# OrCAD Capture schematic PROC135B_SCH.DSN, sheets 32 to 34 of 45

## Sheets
32 32. SOC WKUP & GPMC: size C; title: SOC WKUP AND SOC GPMC INTERFACE
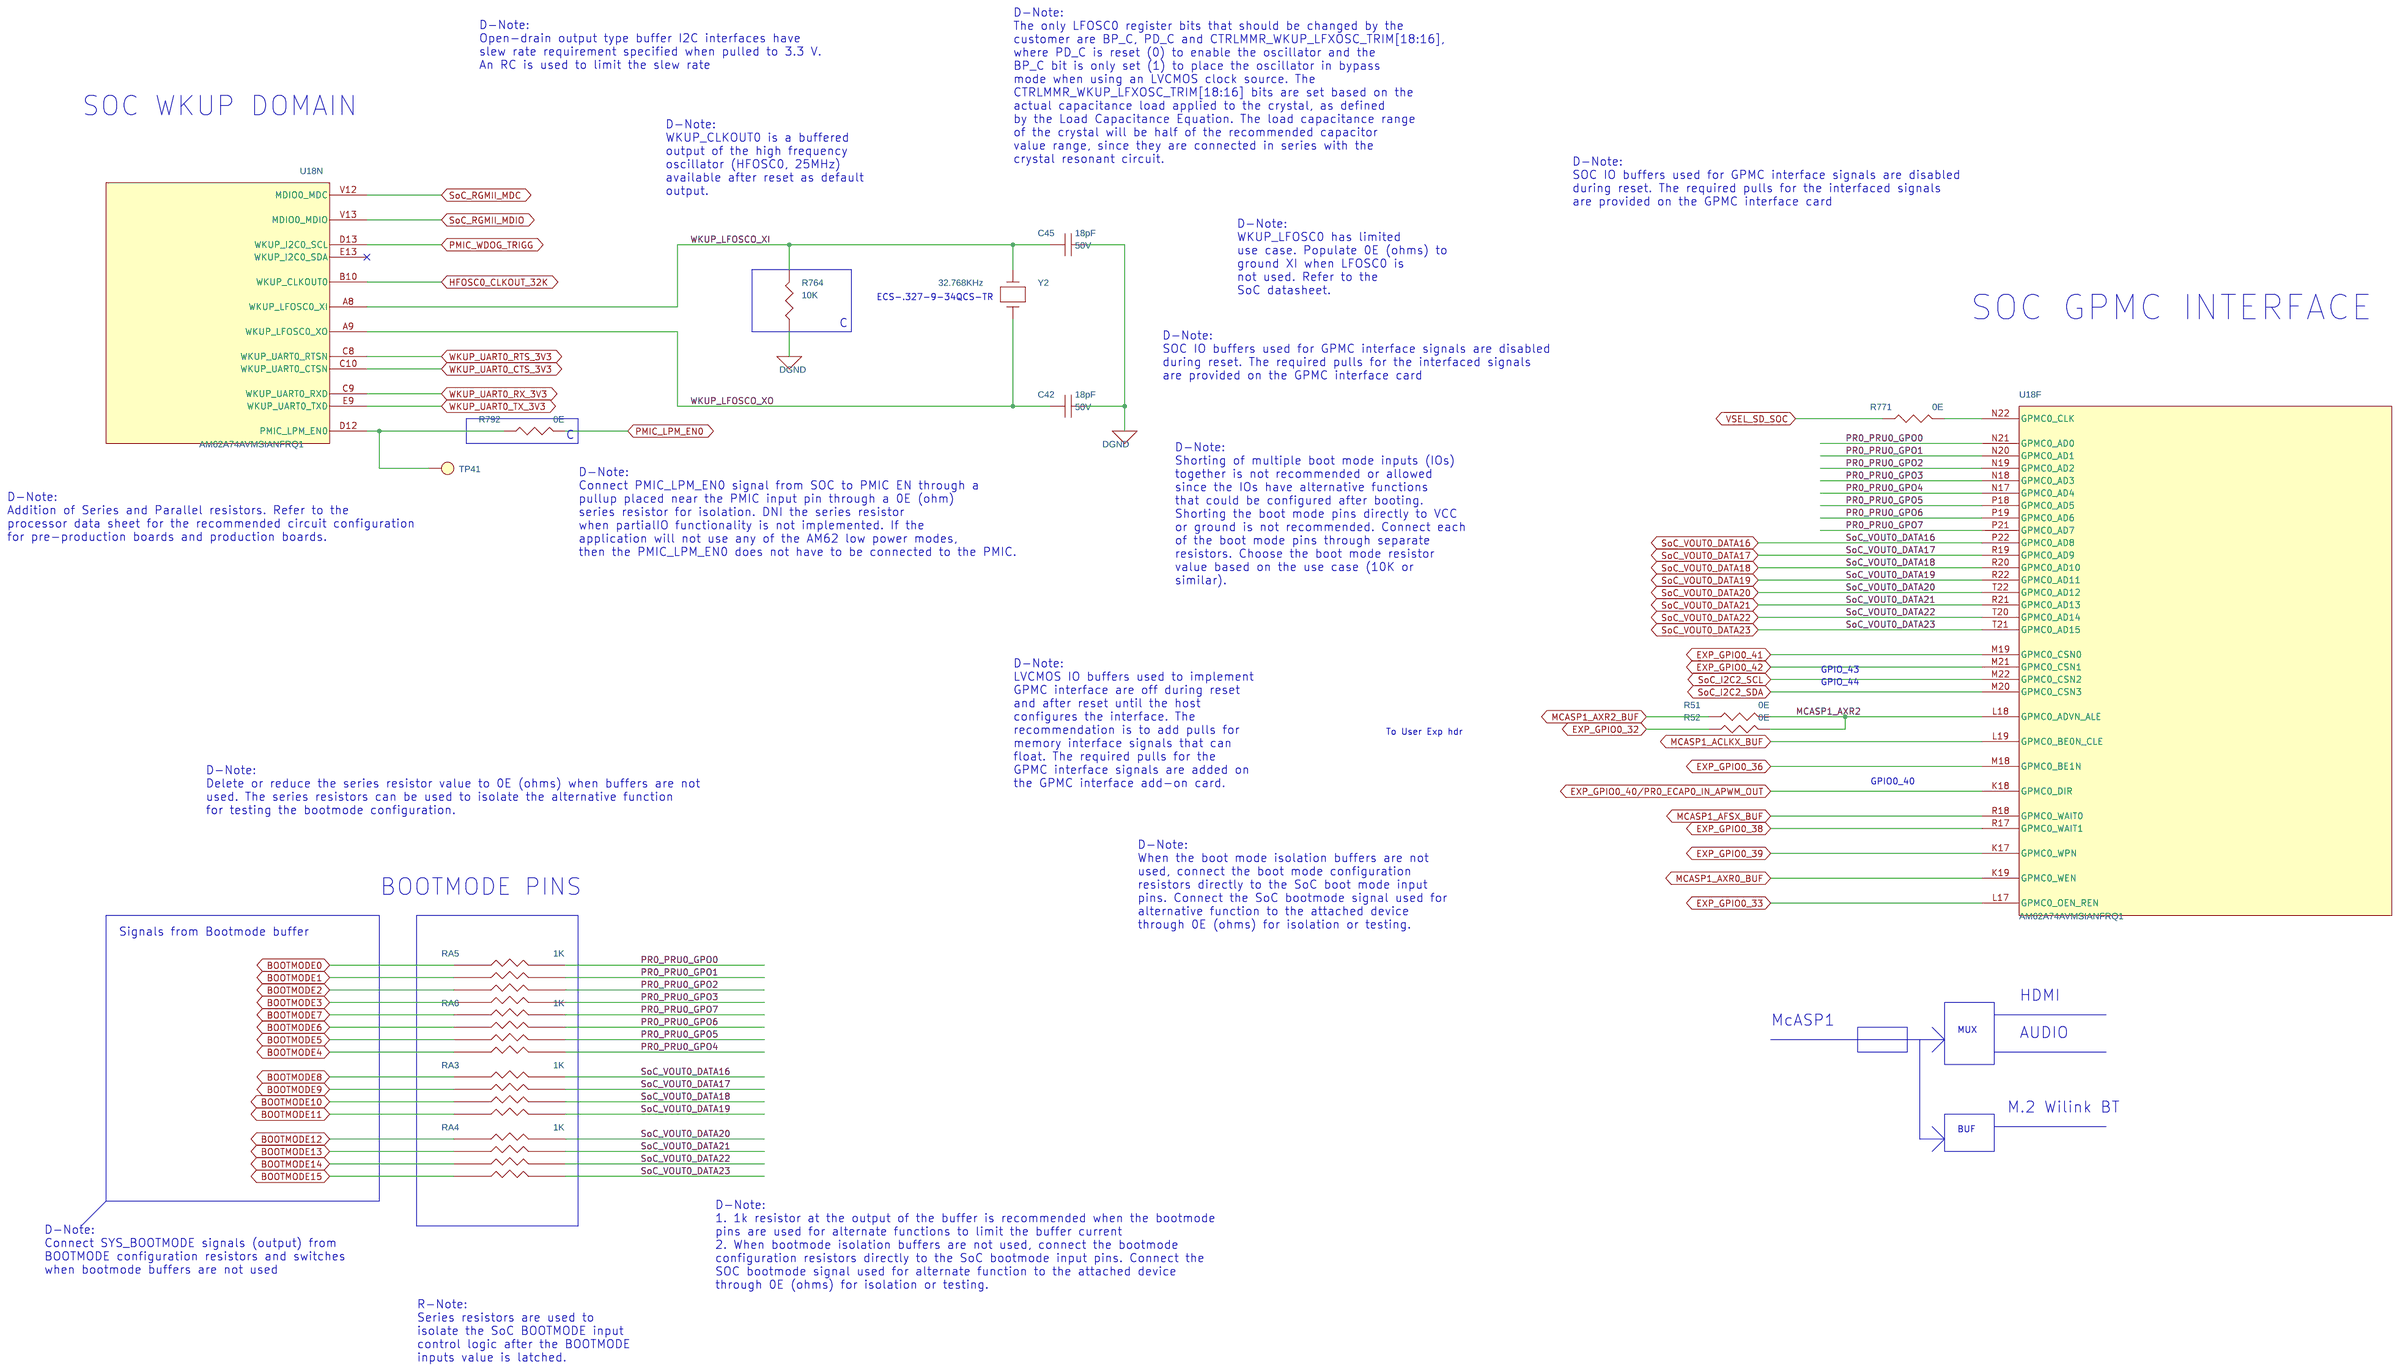
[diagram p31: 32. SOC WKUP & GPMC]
33 33. USER EXPANSION CONNECTOR: size C; title: USER EXPANSION CONNECTOR
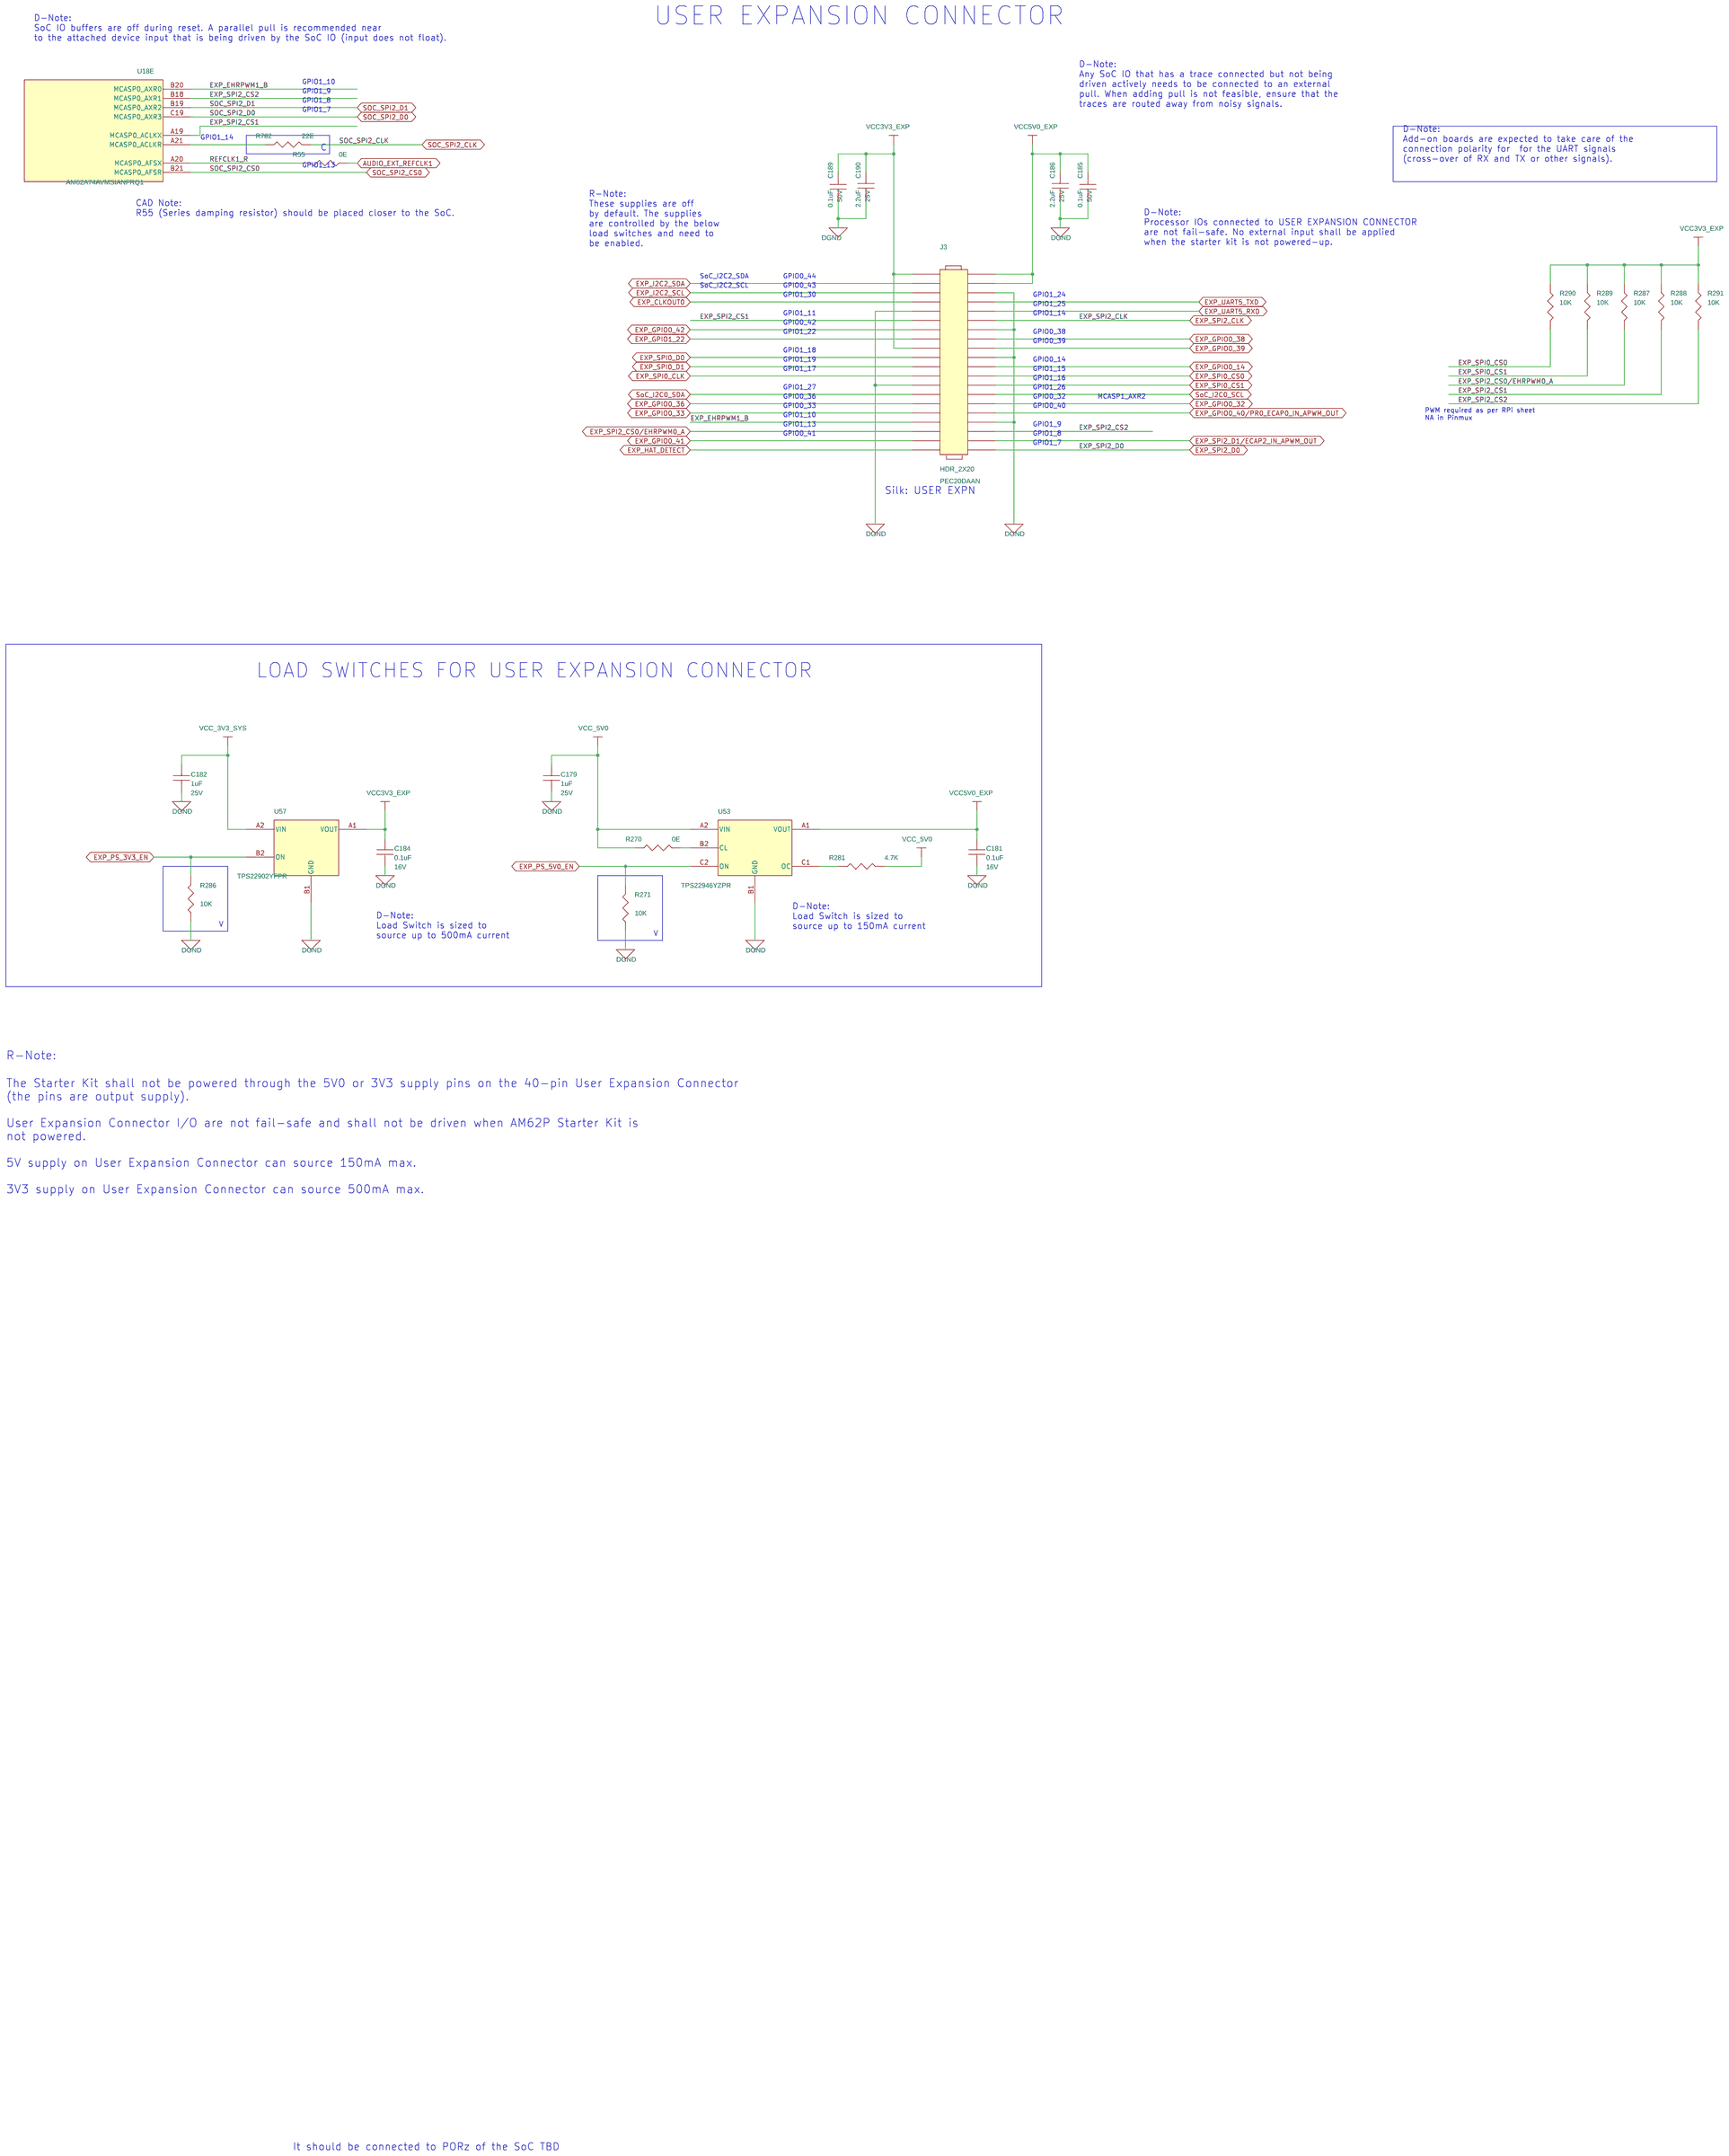
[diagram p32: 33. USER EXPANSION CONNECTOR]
34 34. MCU HEADER: size C; title: SOC-MCU DOMAIN IO and OSC0 AND SOC-MCU IO HEADER
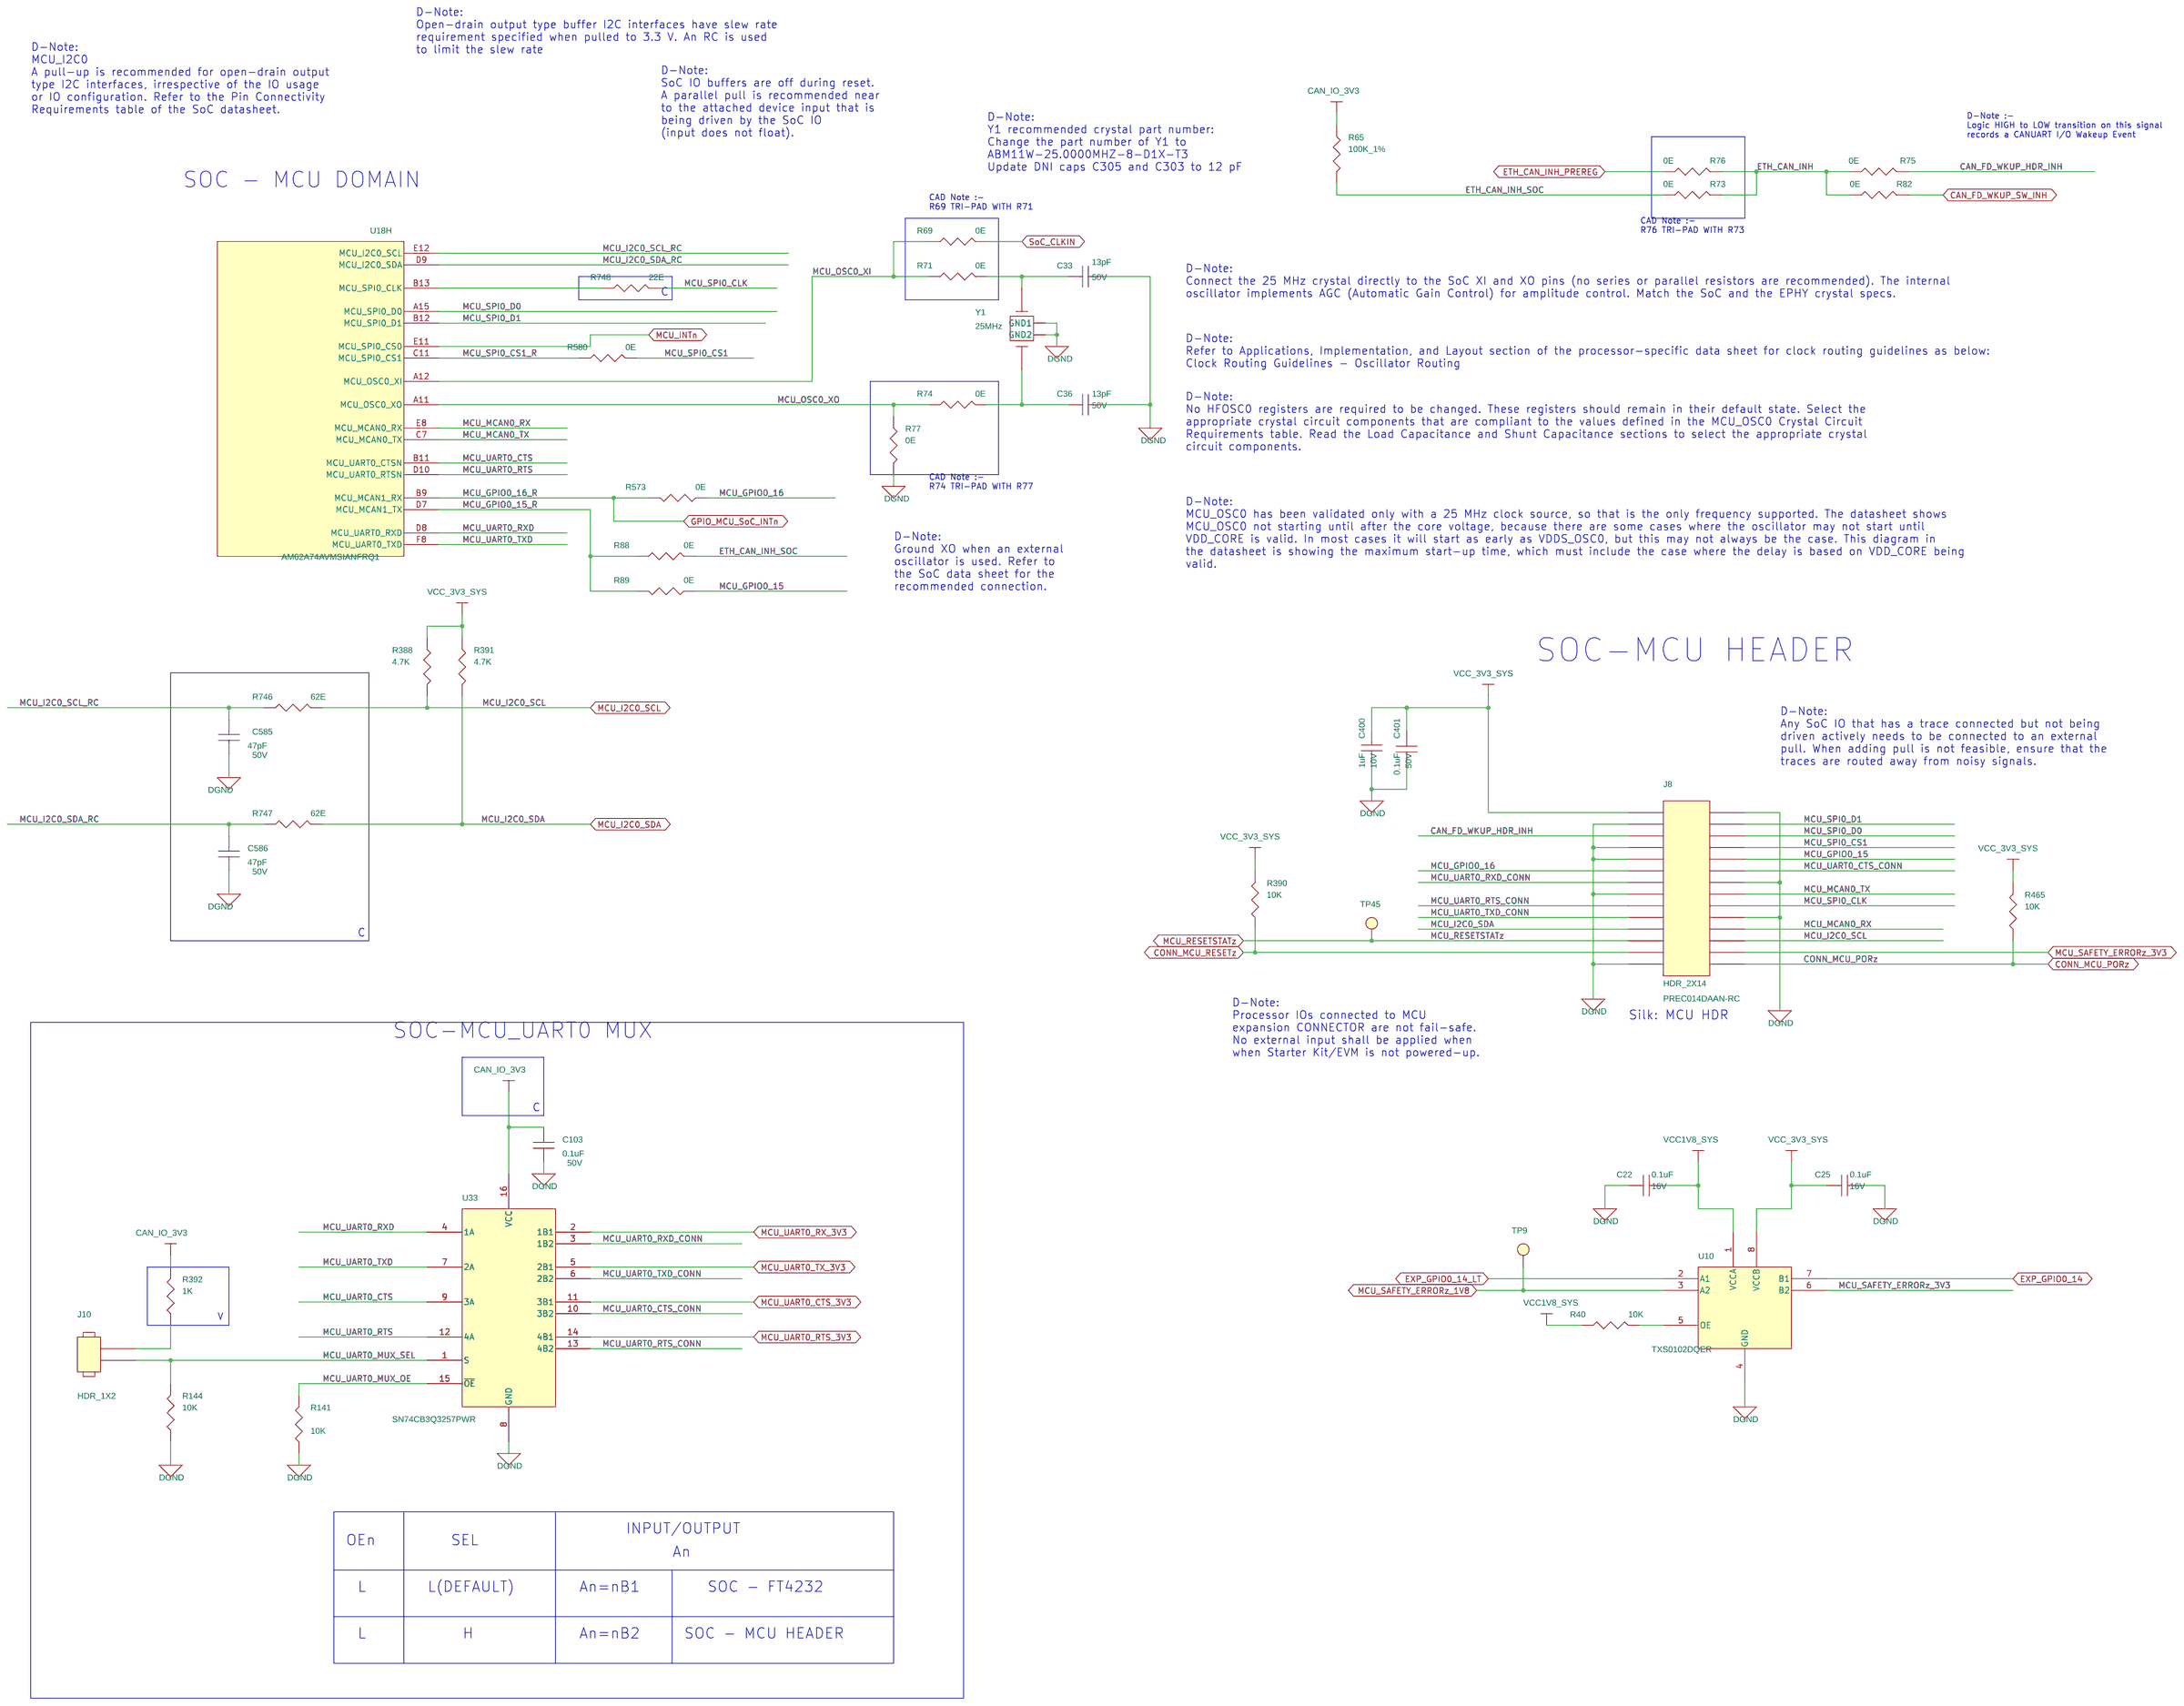
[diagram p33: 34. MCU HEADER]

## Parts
sheet 32. SOC WKUP & GPMC
C42  18pF  [CAP0402_0-75]
C45  18pF  [CAP0402_0-75]
R51  0E  [RES0201_0-5]
R52  0E  [RES0201_0-5]
R764  10K  [RES0201_0-5]
R771  0E  [RES0201_0-5]
R792  0E  [RES0201_0-5]
RA3  1K  [RESA_EXB_0201-4_0-5]
RA4  1K  [RESA_EXB_0201-4_0-5]
RA5  1K  [RESA_EXB_0201-4_0-5]
RA6  1K  [RESA_EXB_0201-4_0-5]
TP41  TP20_SMD  [TP20_SMD]
Y2  32.768KHz  [XTAL_ECS-32_130X60_SMD_0-9]
sheet 33. USER EXPANSION CONNECTOR
C179  1uF  [CAP0402_0-75]
C181  0.1uF  [CAP0201_0-5]
C182  1uF  [CAP0402_0-75]
C184  0.1uF  [CAP0201_0-5]
C185  0.1uF  [CAP0402_0-75]
C186  2.2uF  [CAP0402_0-75]
C189  0.1uF  [CAP0402_0-75]
C190  2.2uF  [CAP0402_0-75]
J3  HDR_2X20  [HDR_2X20_PEC20DAAN_S_T_8-6]
R55  0E  [RES0201_0-5]
R270  0E  [RES0201_0-5]
R271  10K  [RES0201_0-5]
R281  4.7K  [RES0201_0-5]
R286  10K  [RES0201_0-5]
R287  10K  [RES0201_0-5]
R288  10K  [RES0201_0-5]
R289  10K  [RES0201_0-5]
R290  10K  [RES0201_0-5]
R291  10K  [RES0201_0-5]
R782  22E  [RES0201_0-5]
U53  TPS22946YZPR  [DSBGA6_19-68_40X60_0-5]
U57  TPS22902YFPR  [DSBGA4_15-74_30X30_0-5]
sheet 34. MCU HEADER
C22  0.1uF  [CAP0201_0-5]
C25  0.1uF  [CAP0201_0-5]
C33  13pF  [CAP0402_0-75]
C36  13pF  [CAP0402_0-75]
C103  0.1uF  [CAP0402_0-75]
C400  1uF  [CAP0201_0-5]
C401  0.1uF  [CAP0402_0-75]
C585  47pF  [CAP0201_0-5]
C586  47pF  [CAP0201_0-5]
J8  HDR_2X14  [HDR_14X2_100_S_T]
J10  HDR_1X2  [HDR_1X2_90120-0122_S_T_5-6]
R40  10K  [RES0201_0-5]
R65  100K_1%  [RES0402_0-5]
R69  0E  [RES0201_0-5]
R71  0E  [RES0201_0-5]
R73  0E  [RES0201_0-5]
R74  0E  [RES0201_0-5]
R75  0E  [RES0201_0-5]
R76  0E  [RES0201_0-5]
R77  0E  [RES0201_0-5]
R82  0E  [RES0201_0-5]
R88  0E  [RES0201_0-5]
R89  0E  [RES0201_0-5]
R141  10K  [RES0201_0-5]
R144  10K  [RES0201_0-5]
R388  4.7K  [RES0201_0-5]
R390  10K  [RES0201_0-5]
R391  4.7K  [RES0201_0-5]
R392  1K  [RES0402_0-5]
R465  10K  [RES0201_0-5]
R573  0E  [RES0201_0-5]
R580  0E  [RES0201_0-5]
R746  62E  [RES0201_0-5]
R747  62E  [RES0201_0-5]
R748  22E  [RES0201_0-5]
TP9  TP20_SMD  [TP20_SMD]
TP45  TP20_SMD  [TP20_SMD]
U10  TXS0102DQER  [X2SON8_TXS0102_40X60_0-4]
U18  AM62A74AVMSIANFRQ1  [FBGA484_31-49_710X710_2-7]  (sections A,B,C,D,E,F,G,H,I,J,K,L,M,N,O,P,Q)
U33  SN74CB3Q3257PWR  [TSSOP16_25-59_205X180]
Y1  25MHz  [XTAL4_ABM11W_80X70_SMD_0-5]

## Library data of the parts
C42 C45 = CAP: CAP CERAMIC 18pF 50V 5% HI-Q C0G(NP0) AUTO 0402; Chkd/date: PRADEEP/080224; Crtd /date: TAMILARASU/080224; Custom_Duty: 15%; Customs_HS_Code: 85322990; Distributor_name: NA; Distributor_part_number: NA; Footprint Path: Y:\MIS_DATABASE\Library\ALTIUM_TOOL\PCB_FOOTPRINTS\Altium_Footprint_Lib.PcbLib; Height: 0.55MM; Library Path: Y:\MIS_DATABASE\Library\ALTIUM_TOOL\SCHEMATICS_PARTS\MS_DISCRETE_Library.schlib; Mfr_name: MURATA; Mfr_part_number: GCQ1555C1H180JB01; Mistral Part No: 120024020020-R; Package: 0402; Part_type: CAPACITORS\CERAMIC; Project: AM62D_EVM; RoHS: RoHS; Temperature: -55°C+125°C; Tolerance: 5%; Voltage: 50V; Wattage: NA; Weight: NA; Datasheet: Y:\MIS_DATABASE\DATASHEETS\CAPACITORS\GCQ1555C1H180JB01.PDF
R51 R52 R55 R69 R71 R73-R75 R77 R88 R89 R270 R573 R580 R771 R792 = RESISTOR: RES 0E 1/20W 5% 0201; Chkd/date: NAVEED/301214; Crtd /date: MUDDU/120710; Custom_Duty: 15%; Customs_HS_Code: 85332119; Distributor_name: DIGIKEY; Distributor_part_number: 311-0.0NCT-ND; Footprint Path: Y:\MIS_DATABASE\Library\ALTIUM_TOOL\PCB_FOOTPRINTS\Altium_Footprint_Lib.PcbLib; Height: 0.26MM; Library Path: Y:\MIS_DATABASE\Library\ALTIUM_TOOL\SCHEMATICS_PARTS\MS_DISCRETE_Library.schlib; Mfr_name: YAGEO AMERICA; Mfr_part_number: RC0201JR-070RL; Mistral Part No: 110010070067-R; Package: 0201; Part_type: RESISTORS\FIXED; Project: PB_BUGBASE; RoHS: RoHS; Temperature: -55°C+125°C; Tolerance: 5%; Voltage: NA; Wattage: 1/20W; Weight: 0.17mg; Datasheet: Y:\MIS_DATABASE\DATASHEETS\RESISTORS\RCXXXXL-SER_MAR18.PDF
R40 R141 R144 R271 R286-R291 R390 R465 R764 = RESISTOR: RES 10K 1/20W 5% 0201; Chkd/date: MANIRAJA/050517; Crtd /date: MANIRAJA/050517; Custom_Duty: 15%; Customs_HS_Code: 85332119; Distributor_name: DIGIKEY; Distributor_part_number: 311-10KNCT-ND; Footprint Path: Y:\MIS_DATABASE\Library\ALTIUM_TOOL\PCB_FOOTPRINTS\Altium_Footprint_Lib.PcbLib; Height: 0.26MM; Library Path: Y:\MIS_DATABASE\Library\ALTIUM_TOOL\SCHEMATICS_PARTS\MS_DISCRETE_Library.schlib; Mfr_name: YAGEO AMERICA; Mfr_part_number: RC0201JR-0710KL; Mistral Part No: 110010070051-R; Package: 0201; Part_type: RESISTORS\FIXED; Project: GOLDEN-I LITE; RoHS: RoHS; Temperature: -55°C+125°C; Tolerance: 5%; Voltage: NA; Wattage: 1/20W; Weight: 0.17mg; Datasheet: Y:\MIS_DATABASE\DATASHEETS\RESISTORS\RCXXXXL-SER_MAR18.PDF
RA3-RA6 = RESARR_ISO4: RES ARRAY 1K 31mW 5% 0201-4; Chkd/date: NAVEED/110515; Crtd /date: VASANTHA/080515; Custom_Duty: 15%; Customs_HS_Code: 85332119; Distributor_name: DIGIKEY; Distributor_part_number: Y6102CT-ND; Footprint Path: Y:\MIS_DATABASE\Library\ALTIUM_TOOL\PCB_FOOTPRINTS\Altium_Footprint_Lib.PcbLib; Height: 0.45MM; Library Path: Y:\MIS_DATABASE\Library\ALTIUM_TOOL\SCHEMATICS_PARTS\MS_DISCRETE_Library.schlib; Mfr_name: PANASONIC-ECG; Mfr_part_number: EXB-18V102JX; Mistral Part No: 110015050003-R; Package: 0201-4; Part_type: RESISTORS\ARRAY; Project: FREE SCALE NANO; RoHS: RoHS; Temperature: -55°C+125°C; Tolerance: 5%; Voltage: NA; Wattage: 31mW; Weight: 1mg; Datasheet: Y:\MIS_DATABASE\DATASHEETS\RESISTORS\EXB-18V.PDF
TP9 TP41 TP45 = TESTPOINT: TESTPOINT CIR 20 SMD; Chkd/date: SHREESHAIL/171006; Crtd /date: MAZHAR/171006; Custom_Duty: NA; Customs_HS_Code: NA; Distributor_name: NA; Distributor_part_number: NA; Footprint Path: Y:\MIS_DATABASE\Library\ALTIUM_TOOL\PCB_FOOTPRINTS\Altium_Footprint_Lib.PcbLib; Height: NA; Library Path: Y:\MIS_DATABASE\Library\ALTIUM_TOOL\SCHEMATICS_PARTS\MS_DISCRETE_Library.schlib; MECHANICAL 3D STEP FILE: NA; Mfr_name: LOCAL; Mistral Part No: NA; Package: SMD; Project: BT MODULE_CSRBC04; RoHS: NA; Temperature: NA; Tolerance: NA; Voltage: NA; Wattage: NA; Weight: NA; Datasheet: NA
Y2 = CRY: CRY 32.768KHz 9pF SMD; Chkd/date: VASANTHA/090419; Crtd /date: ALVY/090419; Custom_Duty: 24%; Customs_HS_Code: 85439000; Distributor_name: DIGIKEY; Distributor_part_number: XC2160CT-ND; Footprint Path: Y:\MIS_DATABASE\Library\ALTIUM_TOOL\PCB_FOOTPRINTS\Altium_Footprint_Lib.PcbLib; Height: 0.90MM; Library Path: Y:\MIS_DATABASE\Library\ALTIUM_TOOL\SCHEMATICS_PARTS\MS_DISCRETE_Library.schlib; Mfr_name: ECS INC; Mfr_part_number: ECS-.327-9-34QCS-TR; Mistral Part No: 130019040003-R; Package: SMD; Part_type: CRYSTAL; Project: J7ES_SOM_DUAL-LEO_PMIC; RoHS: RoHS; Temperature: -40°C+125°C; Tolerance: NA; Voltage: NA; Wattage: NA; Weight: 16mg; Datasheet: Y:\MIS_DATABASE\DATASHEETS\MISC\CRY_OSC\ECS-34Q.PDF
C179 C182 = CAP: CAP CERAMIC 1uF 25V 10% X5R AUTO 0402; Chkd/date: MANIRAJA/290318; Crtd /date: ALVY/280318; Custom_Duty: 15%; Customs_HS_Code: 85322990; Distributor_name: DIGIKEY; Distributor_part_number: 490-12263-1-ND; Footprint Path: Y:\MIS_DATABASE\Library\ALTIUM_TOOL\PCB_FOOTPRINTS\Altium_Footprint_Lib.PcbLib; Height: 0.55MM; Library Path: Y:\MIS_DATABASE\Library\ALTIUM_TOOL\SCHEMATICS_PARTS\MS_DISCRETE_Library.schlib; Mfr_name: MURATA; Mfr_part_number: GRT155R61E105KE01D; Mistral Part No: 120019040035-R; Package: 0402; Part_type: CAPACITORS\CERAMIC; Project: NPOL_SAR_ADC; RoHS: RoHS; Temperature: -55°C+85°C; Tolerance: 10%; Voltage: 25V; Wattage: NA; Weight: 0.65mg; Datasheet: Y:\MIS_DATABASE\DATASHEETS\CAPACITORS\GRT155R61E105KE01D.PDF
C181 C184 = CAP: CAP CERAMIC 0.1uF 16V 10% X5R 0201; Chkd/date: PRADEEP/130623; Crtd /date: PRADEEP/130623; Custom_Duty: 15%; Customs_HS_Code: 85322990; Distributor_name: NA; Distributor_part_number: NA; Footprint Path: Y:\MIS_DATABASE\Library\ALTIUM_TOOL\PCB_FOOTPRINTS\Altium_Footprint_Lib.PcbLib; Height: 0.33MM; Library Path: Y:\MIS_DATABASE\Library\ALTIUM_TOOL\SCHEMATICS_PARTS\MS_DISCRETE_Library.schlib; Mfr_name: MURATA; Mfr_part_number: GRT033R61C104KE01; Mistral Part No: 120022060019-R; Package: 0201; Part_type: CAPACITORS\CERAMIC; Project: AM62P_SK; RoHS: RoHS; Temperature: -55°C+85°C; Tolerance: 10%; Voltage: 16V; Wattage: NA; Weight: 0.33mg; Datasheet: Y:\MIS_DATABASE\DATASHEETS\CAPACITORS\GRT033R61C104KE01XX.PDF
C103 C185 C189 C401 = CAP: CAP CERAMIC 0.1uF 50V 10% X7R AUTO 0402; Alt_Mfr_name: YAGEO AMERICA; Alt_Mfr_part_number: CC0402KRX5R8BB104; Chkd/date: MANIRAJA/250221; Crtd /date: ALVY/240221; Custom_Duty: 15%; Customs_HS_Code: 85322990; Distributor_name: MOUSER; Distributor_part_number: 81-GRT155R71H104KE1D; Footprint Path: Y:\MIS_DATABASE\Library\ALTIUM_TOOL\PCB_FOOTPRINTS\Altium_Footprint_Lib.PcbLib; Height: 0.55MM; Library Path: Y:\MIS_DATABASE\Library\ALTIUM_TOOL\SCHEMATICS_PARTS\MS_DISCRETE_Library.schlib; Mfr_name: MURATA; Mfr_part_number: GRT155R71H104KE01D; Mistral Part No: 120019030005-R; Package: 0402; Part_type: CAPACITORS\CERAMIC; Project: TI_DRA821 SK EVM BRD; RoHS: RoHS; Temperature: -55°C+125°C; Tolerance: 10%; Voltage: 50V; Wattage: NA; Weight: NA; Datasheet: Y:\MIS_DATABASE\DATASHEETS\CAPACITORS\GRT155R71H104KE01.PDF
C186 C190 = CAP: CAP CERAMIC 2.2uF 25V 10% X5R AUTO 0402; Chkd/date: MANIRAJA/240920; Crtd /date: ALVY/240920; Custom_Duty: 15%; Customs_HS_Code: 85322990; Distributor_name: DIGIKEY; Distributor_part_number: 490-12267-1-ND; Footprint Path: Y:\MIS_DATABASE\Library\ALTIUM_TOOL\PCB_FOOTPRINTS\Altium_Footprint_Lib.PcbLib; Height: 0.70MM; Library Path: Y:\MIS_DATABASE\Library\ALTIUM_TOOL\SCHEMATICS_PARTS\MS_DISCRETE_Library.schlib; Mfr_name: MURATA; Mfr_part_number: GRT155R61E225KE13D; Mistral Part No: 120020090019-R; Package: 0402; Part_type: CAPACITORS\CERAMIC; Project: ECU_RO; RoHS: RoHS; Temperature: -55°C+85°C; Tolerance: 10%; Voltage: 25V; Wattage: NA; Weight: 0.65mg; Datasheet: Y:\MIS_DATABASE\DATASHEETS\CAPACITORS\GRT155R61E225KE13.PDF
J3 = HEADER_20X2: CON HDR 2X20 2.54MM PITCH ST TH; Chkd/date: MANIRAJA/261020; Crtd /date: MANIRAJA/261020; Custom_Duty: 24%; Customs_HS_Code: 85369090; Distributor_name: DIGIKEY; Distributor_part_number: S2012E-20-ND; Footprint Path: Y:\MIS_DATABASE\Library\ALTIUM_TOOL\PCB_FOOTPRINTS\Altium_Footprint_Lib.PcbLib; Height: 8.58MM; Library Path: Y:\MIS_DATABASE\Library\ALTIUM_TOOL\SCHEMATICS_PARTS\MS_CONNECTOR_Library.schlib; Mfr_name: SULLINS CONNECTOR; Mfr_part_number: PEC20DAAN; Mistral Part No: 150020100013-R; Package: THRU-HOLE; Part_type: CONNECTOR\HEADERS; Project: AM64X_SKEVM; RoHS: RoHS; Temperature: -65°C+125°C; Tolerance: NA; Voltage: NA; Wattage: NA; Weight: NA; Datasheet: Y:\MIS_DATABASE\DATASHEETS\CONNECTORS\XXCXXDXXN.PDF
R281 R388 R391 = RESISTOR: RES 4.7K 1/20W 5% 0201; Chkd/date: MANIRAJA/200921; Crtd /date: ALVY/200921; Custom_Duty: 15%; Customs_HS_Code: 85332119; Distributor_name: DIGIKEY; Distributor_part_number: 311-4.7KNCT-ND; Footprint Path: Y:\MIS_DATABASE\Library\ALTIUM_TOOL\PCB_FOOTPRINTS\Altium_Footprint_Lib.PcbLib; Height: 0.26MM; Library Path: Y:\MIS_DATABASE\Library\ALTIUM_TOOL\SCHEMATICS_PARTS\MS_DISCRETE_Library.schlib; Mfr_name: YAGEO AMERICA; Mfr_part_number: RC0201JR-074K7L; Mistral Part No: 110021090007-R; Package: 0201; Part_type: RESISTORS\FIXED; Project: TI_AM62x SKEVM_BRD; RoHS: RoHS; Temperature: -55°C+125°C; Tolerance: 5%; Voltage: NA; Wattage: 1/20W; Weight: 0.17mg; Datasheet: Y:\MIS_DATABASE\DATASHEETS\RESISTORS\RCXXXXL-SER_MAR18.PDF
R748 R782 = RESISTOR: RES 22E 1/20W 5% 0201; Chkd/date: PRADEEP/220424; Crtd /date: SHANKARI/220424; Custom_Duty: 15%; Customs_HS_Code: 85332119; Distributor_name: DIGIKEY; Distributor_part_number: 311-22NCT-ND; Footprint Path: Y:\MIS_DATABASE\Library\ALTIUM_TOOL\PCB_FOOTPRINTS\Altium_Footprint_Lib.PcbLib; Height: 0.26MM; Library Path: Y:\MIS_DATABASE\Library\ALTIUM_TOOL\SCHEMATICS_PARTS\MS_DISCRETE_Library.schlib; Manufacturer: YAGEO; Mfr_name: YAGEO; Mfr_part_number: RC0201JR-0722RL; Mistral Part No: 110024040012-R; Package: 0201; Part_type: RESISTORS\FIXED; Project: J7AEN_SKEVM; RoHS: RoHS; Temperature: -55°C+125°C; Tolerance: 5%; Voltage: NA; Wattage: 1/20W; Weight: NA; Datasheet: Y:\MIS_DATABASE\DATASHEETS\RESISTORS\RC0201JR-0722RL.PDF
U53 = TPS22946_DSBGA6: IC CURRENT-LIMITED LOAD SWITCH WITH SHUTOFF AUTO-RESTART AND OVERCURRENT CONDITION TIME-OUT DSBGA6; Chkd/date: MANIRAJA/220121; Crtd /date: ALVY/220121; Custom_Duty: 15%; Customs_HS_Code: 85423100; Distributor_name: DIGIKEY; Distributor_part_number: 296-25219-1-ND; Footprint Path: Y:\MIS_DATABASE\Library\ALTIUM_TOOL\PCB_FOOTPRINTS\Altium_Footprint_Lib.PcbLib; Height: 0.50MM; Library Path: Y:\MIS_DATABASE\Library\ALTIUM_TOOL\SCHEMATICS_PARTS\MS_MISCPOWER_Library.schlib; Mfr_name: TEXAS INSTRUMENTS; Mistral Part No: 142021010016-R; Package: DSBGA6; Part_type: ICS\POWER\MANAGEMENT; Project: AM64X_SKEVM; RoHS: RoHS; Temperature: -40°C+85°C; Tolerance: NA; Voltage: NA; Wattage: NA; Weight: 1.7mg; Datasheet: Y:\MIS_DATABASE\DATASHEETS\ICS\POWER\TPS22946.PDF
U57 = TPS22912CYZVR_DSBGA4: IC 3.6V 500mA 78mE ON-RESISTANCE LOAD SWITCH WITH CONTROLLED TURNON DSBGA4; Chkd/date: MANIRAJA/170920; Crtd /date: ALVY/160920; Custom_Duty: 15%; Customs_HS_Code: 85423100; Distributor_name: DIGIKEY; Distributor_part_number: 296-24472-1-ND; Footprint Path: Y:\MIS_DATABASE\Library\ALTIUM_TOOL\PCB_FOOTPRINTS\Altium_Footprint_Lib.PcbLib; Height: 0.50MM; Library Path: Y:\MIS_DATABASE\Library\ALTIUM_TOOL\SCHEMATICS_PARTS\MS_MISCPOWER_Library.schlib; Mfr_name: TEXAS INSTRUMENTS; Mistral Part No: 142020090007-R; Package: DSBGA4; Part_type: ICS\POWER; Project: AM64X_SKEVM; RoHS: RoHS; Temperature: -40°C+85°C; Tolerance: NA; Voltage: NA; Wattage: NA; Weight: 0.7mg; Datasheet: Y:\MIS_DATABASE\DATASHEETS\ICS\POWER\TPS22901-2-3.PDF
C22 C25 = CAP: CAP CERAMIC 0.1uF 16V 10% X5R 0201; Alt_Mfr_name: YAGEO AMERICA; Alt_Mfr_part_number: CC0402KRX5R8BB104; Chkd/date: PRADEEP/130623; Crtd /date: PRADEEP/130623; Custom_Duty: 15%; Customs_HS_Code: 85322990; Distributor_name: NA; Distributor_part_number: NA; Footprint Path: Y:\MIS_DATABASE\Library\ALTIUM_TOOL\PCB_FOOTPRINTS\Altium_Footprint_Lib.PcbLib; Height: 0.33MM; Library Path: Y:\MIS_DATABASE\Library\ALTIUM_TOOL\SCHEMATICS_PARTS\MS_DISCRETE_Library.schlib; Mfr_name: MURATA; Mfr_part_number: GRT033R61C104KE01; Mistral Part No: 120022060019-R; Package: 0201; Part_type: CAPACITORS\CERAMIC; Project: AM62P_SK; RoHS: RoHS; Temperature: -55°C+85°C; Tolerance: 10%; Voltage: 16V; Wattage: NA; Weight: 0.33mg; Datasheet: Y:\MIS_DATABASE\DATASHEETS\CAPACITORS\GRT033R61C104KE01XX.PDF
C33 C36 = CAP: CAP CERAMIC 13pF 50V 5% C0G(NP0) 0402; Chkd/date: VASANTHA/090317; Crtd /date: MANIRAJA/090317; Custom_Duty: 15%; Customs_HS_Code: 85322990; Distributor_name: DIGIKEY; Distributor_part_number: 490-5925-1-ND; Footprint Path: Y:\MIS_DATABASE\Library\ALTIUM_TOOL\PCB_FOOTPRINTS\Altium_Footprint_Lib.PcbLib; Height: 0.55MM; Library Path: Y:\MIS_DATABASE\Library\ALTIUM_TOOL\SCHEMATICS_PARTS\MS_DISCRETE_Library.schlib; Mfr_name: MURATA; Mfr_part_number: GRM1555C1H130JA01D; Mistral Part No: 120017030004-R; Package: 0402; Part_type: CAPACITORS\CERAMIC; Project: SD820_NANO_SOM; RoHS: RoHS; Temperature: -55°C+125°C; Tolerance: 5%; Voltage: 50V; Wattage: NA; Weight: 6mg; Datasheet: Y:\MIS_DATABASE\DATASHEETS\CAPACITORS\MURATA-GXX-SER_NOV17.PDF
C400 = CAP: CAP CERAMIC 1uF 10V 20% X6S 0201; Chkd/date: PRADEEP/130623; Crtd /date: PRADEEP/130623; Custom_Duty: 15%; Customs_HS_Code: 85322990; Distributor_name: DIGIKEY; Distributor_part_number: 490-GRT033C81A105ME13DTR-ND; Footprint Path: Y:\MIS_DATABASE\Library\ALTIUM_TOOL\PCB_FOOTPRINTS\Altium_Footprint_Lib.PcbLib; Height: 0.39MM; Library Path: Y:\MIS_DATABASE\Library\ALTIUM_TOOL\SCHEMATICS_PARTS\MS_DISCRETE_Library.schlib; Mfr_name: MURATA; Mfr_part_number: GRT033C81A105ME13D; Mistral Part No: 120022060020-R; Package: 0201; Part_type: CAPACITORS\CERAMIC; Project: AM62P_SK; RoHS: RoHS; Temperature: -55°C+105°C; Tolerance: 20%; Voltage: 10V; Wattage: NA; Weight: NA; Datasheet: Y:\MIS_DATABASE\DATASHEETS\CAPACITORS\GRT033C81A105ME13D.PDF
C585 C586 = CAP: CAP CERAMIC 47pF 50V 5% C0G(NP0) AUTO 0201; Chkd/date: MANIRAJA/311221; Crtd /date: ALVY/301221; Custom_Duty: 15%; Customs_HS_Code: 85322990; Distributor_name: MOUSER; Distributor_part_number: 81-GRT0335C1H470JA2D; Footprint Path: Y:\MIS_DATABASE\Library\ALTIUM_TOOL\PCB_FOOTPRINTS\Altium_Footprint_Lib.PcbLib; Height: 0.33MM; Library Path: Y:\MIS_DATABASE\Library\ALTIUM_TOOL\SCHEMATICS_PARTS\MS_DISCRETE_Library.schlib; Mfr_name: MURATA; Mfr_part_number: GRT0335C1H470JA02D; Mistral Part No: 120021120018-R; Package: 0201; Part_type: CAPACITORS\CERAMIC; Project: AM62Q_SKEVM_BRD; RoHS: RoHS; Temperature: -55°C+125°C; Tolerance: 5%; Voltage: 50V; Wattage: NA; Weight: 0.33mg; Datasheet: Y:\MIS_DATABASE\DATASHEETS\CAPACITORS\GRT0335C1H470JA02.PDF
J8 = HEADER_14x2: CON HDR 2X14 2.54MM PITCH ST TH; Chkd/date: NAVEED/280515; Crtd /date: VASANTHA/111114; Custom_Duty: 0.24; Customs_HS_Code: 85369090; Distributor_name: DIGIKEY; Distributor_part_number: S2012EC-14-ND; Height: 8.34MM; Mfr_name: SULLINS; Mfr_part_number: PREC014DAAN-RC; Mistral Part No: 150014110005-R; Package: THRU-HOLE; Part_type: CONNECTOR\HEADERS; Project: GALILEO_EVM; RoHS: RoHS; Temperature: -40°C+105°C; Tolerance: NA; Voltage: NA; Wattage: NA; Weight: NA; Datasheet: Y:\MIS_DATABASE\DATASHEETS\CONNECTORS\PRXXXN-RC.PDF
J10 = HEADER_2X1: CON HDR 1X2 2.54MM PITCH ST TH; Chkd/date: NAVEED/210714; Crtd /date: USMAN/031012; Custom_Duty: 24%; Customs_HS_Code: 85369090; Distributor_name: DIGIKEY; Distributor_part_number: WM8072-ND; Footprint Path: Y:\MIS_DATABASE\Library\ALTIUM_TOOL\PCB_FOOTPRINTS\Altium_Footprint_Lib.PcbLib; Height: 5.60MM; Library Path: Y:\MIS_DATABASE\Library\ALTIUM_TOOL\SCHEMATICS_PARTS\MS_CONNECTOR_Library.schlib; Mfr_name: MOLEX; Mfr_part_number: 90120-0122; Mistral Part No: 150012100005-R; Package: THRU-HOLE; Part_type: CONNECTOR\HEADERS; Project: NPOL_FEP; RoHS: RoHS; Temperature: -55°C+125°C; Tolerance: NA; Voltage: NA; Wattage: NA; Weight: 122mg; Datasheet: Y:\MIS_DATABASE\DATASHEETS\CONNECTORS\90120-XX.PDF
R65 = RESISTOR: RES 100K 1/10W 1% 0402; Chkd/date: VASANTHA/201216; Crtd /date: MAZHAR/130306; Custom_Duty: 15%; Customs_HS_Code: 85332119; Distributor_name: DIGIKEY; Distributor_part_number: P100KLCT-ND; Footprint Path: Y:\MIS_DATABASE\Library\ALTIUM_TOOL\PCB_FOOTPRINTS\Altium_Footprint_Lib.PcbLib; Height: 0.40MM; Library Path: Y:\MIS_DATABASE\Library\ALTIUM_TOOL\SCHEMATICS_PARTS\MS_DISCRETE_Library.schlib; Mfr_name: PANASONIC-ECG; Mfr_part_number: ERJ-2RKF1003X; Mistral Part No: 110009030187-R; Package: 0402; Part_type: RESISTORS\FIXED; Project: J32; RoHS: RoHS; Temperature: -55°C+155°C; Tolerance: 1%; Voltage: NA; Wattage: 1/10W; Weight: 0.8mg; Datasheet: Y:\MIS_DATABASE\DATASHEETS\RESISTORS\PAN-ERJSER_NOV17.PDF
R76 R82 = RESISTOR: RES 0E 1/20W 5% 0201; Chkd/date: NAVEED/301214; Crtd /date: MUDDU/120710; Custom_Duty: 15%; Customs_HS_Code: 85332119; Distributor_name: DIGIKEY; Distributor_part_number: 311-0.0NCT-ND; Footprint Path: Y:\MIS_DATABASE\Library\ALTIUM_TOOL\PCB_FOOTPRINTS\Altium_Footprint_Lib.PcbLib; Height: 0.26MM; Library Path: Y:\MIS_DATABASE\Library\ALTIUM_TOOL\SCHEMATICS_PARTS\MS_DISCRETE_Library.schlib; Manufacturer: YAGEO AMERICA; Mfr_name: YAGEO AMERICA; Mfr_part_number: RC0201JR-070RL; Mistral Part No: 110010070067-R; Package: 0201; Part_type: RESISTORS\FIXED; Project: PB_BUGBASE; RoHS: RoHS; Temperature: -55°C+125°C; Tolerance: 5%; Voltage: NA; Wattage: 1/20W; Weight: 0.17mg; Datasheet: Y:\MIS_DATABASE\DATASHEETS\RESISTORS\RCXXXXL-SER_MAR18.PDF
R392 = RESISTOR: RES 1K 1/10W 5% 0402; Chkd/date: VASANTHA/201216; Crtd /date: MAZHAR/230805; Custom_Duty: 15%; Customs_HS_Code: 85332119; Distributor_name: DIGIKEY; Distributor_part_number: P1.0KJCT-ND; Footprint Path: Y:\MIS_DATABASE\Library\ALTIUM_TOOL\PCB_FOOTPRINTS\Altium_Footprint_Lib.PcbLib; Height: 0.40MM; Library Path: Y:\MIS_DATABASE\Library\ALTIUM_TOOL\SCHEMATICS_PARTS\MS_DISCRETE_Library.schlib; Mfr_name: PANASONIC-ECG; Mfr_part_number: ERJ-2GEJ102X; Mistral Part No: 110009030400-R; Package: 0402; Part_type: RESISTORS\FIXED; Project: HSE; RoHS: RoHS; Temperature: -55°C+155°C; Tolerance: 5%; Voltage: NA; Wattage: 1/10W; Weight: 0.8mg; Datasheet: Y:\MIS_DATABASE\DATASHEETS\RESISTORS\PAN-ERJSER_NOV17.PDF
R746 R747 = RESISTOR: RES 62E 1/20W 1% 0201; Chkd/date: PRADEEP/230326; Crtd /date: SHANKARI/230326; Custom_Duty: 15%; Customs_HS_Code: 85332119; Distributor_name: DIGIKEY; Distributor_part_number: P123108CT-ND; Footprint Path: Y:\MIS_DATABASE\Library\ALTIUM_TOOL\PCB_FOOTPRINTS\Altium_Footprint_Lib.PcbLib; Height: 0.26MM; Library Path: Y:\MIS_DATABASE\Library\ALTIUM_TOOL\SCHEMATICS_PARTS\MS_DISCRETE_Library.schlib; Mfr_name: PANASONIC; Mfr_part_number: ERJ-1GNF62R0C; Mistral Part No: 110026030006-R; Package: 0201; Part_type: RESISTORS\FIXED; Project: AM62X_FULTON_REV B; RoHS: RoHS; Temperature: -55°C+125°C; Tolerance: 0.01; Voltage: NA; Wattage: 1/20W; Weight: NA; Datasheet: Y:\MIS_DATABASE\DATASHEETS\RESISTORS\ERJ-1GNF62R0C.PDF
U10 = TXS0102DQX_SON8: IC 2-BIT BI-DIR VOLTAGE-LEVEL TRANSLATOR FOR OPEN-DRAIN AND PUSH-PULL X2SON8; Chkd/date: MANIRAJA/010719; Crtd /date: CHAITHANYA230512; Custom_Duty: 15%; Customs_HS_Code: 85423100; Distributor_name: DIGIKEY; Distributor_part_number: 296-28368-1-ND; Footprint Path: Y:\MIS_DATABASE\Library\ALTIUM_TOOL\PCB_FOOTPRINTS\Altium_Footprint_Lib.PcbLib; Height: 0.40MM; Library Path: Y:\MIS_DATABASE\Library\ALTIUM_TOOL\SCHEMATICS_PARTS\MS_MISCINTERFACE_Library.schlib; Mfr_name: TEXAS INSTRUMENTS; Mistral Part No: 141012050010-R; Package: X2SON8; Part_type: ICS\INTERFACE\LEVEL TRANSLATOR; Project: GEN_3-8_DB; RoHS: RoHS; Temperature: -40°C+85°C; Tolerance: NA; Voltage: NA; Wattage: NA; Weight: 1.2mg; Datasheet: Y:\MIS_DATABASE\DATASHEETS\ICS\INTERFACE\TXS0102-SER.PDF
U18 = AM62A-EVM_SOC_FCBGA484: IC AM62A SK EVM SoC MICROPROCESSOR FCBGA484; Chkd/date: PRADEEP/120225; Crtd /date: SHANKARI/120225; Custom_Duty: 15%; Customs_HS_Code: 85369090; Distributor_name: NA; Distributor_part_number: NA; Footprint Path: Y:\MIS_DATABASE\Library\ALTIUM_TOOL\PCB_FOOTPRINTS\Altium_Footprint_Lib.PcbLib; Height: 2.65MM; Library Path: Y:\MIS_DATABASE\Library\ALTIUM_TOOL\SCHEMATICS_PARTS\MS_MICROPROCESSOR_Library.schlib; Library Ref: AM62A-EVM_SoC_FCBGA484; Mfr_name: TEXAS INSTRUMENTS; Mistral Part No: 141225020003-R; Package: FCBGA484; Part_type: ICS\DIGITAL\MICROPROCESSOR; Project: AM62A_SK_EVM; RoHS: NA; Temperature: NA; Tolerance: NA; Voltage: NA; Wattage: NA; Weight: NA; Datasheet: Y:\MIS_DATABASE\DATASHEETS\ICS\DIGITAL\MICROCONTROLLER\AM62A_SK_EVM.PDF
U33 = SN74CB3Q3257PWR_TSSOP16: IC 4BIT 1-OF-2 FET MULTIPLEXER/DEMULTIPLEXER TSSOP16; Chkd/date: SUHAS/251010; Crtd /date: USMAN/060109; Custom_Duty: 15%; Customs_HS_Code: 85423100; Distributor_name: DIGIKEY; Distributor_part_number: 296-19138-1-ND; Height: 1.20MM; Mfr_name: TEXAS INSTRUMENTS; Mistral Part No: 141009030117-R; Package: TSSOP16; Part_type: ICS\DIGITAL\COMBINATIONAL; Project: OMAP_EVM; RoHS: Sb/ Br FREE; Temperature: -40°C+85°C; Datasheet: Y:\MIS_DATABASE\DATASHEETS\ICS\DIGITAL\COMBINATIONAL\SN74CB3Q3257.PDF
Y1 = CRY4_ABM8G: CRY 25MHz 8pF SMD; Crtd /date: SHANKARI/041125; Custom_Duty: 24%; Customs_HS_Code: 85439000; Distributor_name: DIGIKEY; Distributor_part_number: 535-13853-1-ND; Footprint Path: Y:\MIS_DATABASE\Library\ALTIUM_TOOL\PCB_FOOTPRINTS\Altium_Footprint_Lib.PcbLib; Height: 0.50MM; Library Path: Y:\MIS_DATABASE\Library\ALTIUM_TOOL\SCHEMATICS_PARTS\MS_DISCRETE_Library.schlib; Mfr_name: ABRACON CORPORATION; Mfr_part_number: ABM11W-25.0000MHZ-8-D1X-T3; Mistral Part No: 130025110002-R; Package: SMD; Part_type: CRYSTAL; Project: AM62X_SK_FULTON; RoHS: RoHS; Temperature: -40°C+85°C; Tolerance: NA; Voltage: NA; Wattage: NA; Weight: NA; Datasheet: Y:\MIS_DATABASE\DATASHEETS\MISC\CRY_OSC\ABM11W.PDF

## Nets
DGND: C22.2 C25.1 C33.2 C36.2 C42.2 C45.2 C103.1 C179.2 C181.2 C182.2 C184.2 C185.1 C186.2 C189.1 C190.2 C400.2 C401.1 C585.1 C586.1 J3.6 J3.9 J3.14 J3.20 J3.25 J3.34 J8.2 J8.3 J8.7 J8.9 J8.14 J8.15 J8.20 J8.27 R77.1 R141.2 R144.1 R271.1 R286.1 R764.1 U10.4(GND) U33.8(GND) U53.B1(GND) U57.B1(GND) Y1.2(GND1) Y1.4(GND2) ; also on sheet 10 11 12 13 14 15 16 17 18 19 20 21 22 23 24 25 26 27 28 29 30 31 35 36 37 38 39 40 41 42 43 44
VCC1V8_SYS: C22.1 R40.1 U10.1(VCCA) ; also on sheet 13 18 19 21 37 39 40 42
VCC3V3_EXP: C184.1 C189.2 C190.1 J3.1 J3.17 R287.1 R288.1 R289.1 R290.1 R291.1 U57.A1(VOUT) ; also on sheet 38
VCC5V0_EXP: C181.1 C185.2 C186.1 J3.2 J3.4 U53.A1(VOUT)
VCC_3V3_SYS: C25.2 C182.1 C400.1 C401.2 J8.1 R388.1 R390.2 R391.1 R465.2 U10.8(VCCB) U57.A2(VIN) ; also on sheet 10 11 13 14 18 19 20 22 23 24 26 27 29 30 31 35 36 37 38 39 40 41 42 43
VCC_5V0: C179.1 R270.1 R281.2 U53.A2(VIN) ; also on sheet 10 11 15 35 38 41
AUDIO_EXT_REFCLK1: R55.1 ; also on sheet 41
BOOTMODE0: RA5.1 ; also on sheet 27
BOOTMODE1: RA5.2 ; also on sheet 27
BOOTMODE2: RA5.3 ; also on sheet 27
BOOTMODE3: RA5.4 ; also on sheet 27
BOOTMODE4: RA6.4 ; also on sheet 27
BOOTMODE5: RA6.3 ; also on sheet 27
BOOTMODE6: RA6.2 ; also on sheet 27
BOOTMODE7: RA6.1 ; also on sheet 27
BOOTMODE8: RA3.1 ; also on sheet 27
BOOTMODE9: RA3.2 ; also on sheet 27
BOOTMODE10: RA3.3 ; also on sheet 27
BOOTMODE11: RA3.4 ; also on sheet 27
BOOTMODE12: RA4.1 ; also on sheet 27
BOOTMODE13: RA4.2 ; also on sheet 27
BOOTMODE14: RA4.3 ; also on sheet 27
BOOTMODE15: RA4.4 ; also on sheet 27
CAN_FD_WKUP_HDR_INH: J8.5 R75.1
CAN_FD_WKUP_SW_INH: R82.2 ; also on sheet 44
CAN_IO_3V3: C103.2 R65.1 R392.2 U33.16(VCC) ; also on sheet 13 15 31 44
CONN_MCU_PORz: J8.28 R465.1 ; also on sheet 42
CONN_MCU_RESETz: J8.25 R390.1 ; also on sheet 43
ETH_CAN_INH: R73.2 R75.2 R76.2 R82.1
ETH_CAN_INH_PREREG: R76.1 ; also on sheet 12
ETH_CAN_INH_SOC: R65.2 R73.1 R88.1
EXP_CLKOUT0: J3.7 ; also on sheet 42
EXP_EHRPWM1_B: J3.33 U18.B20(MCASP0_AXR0)
EXP_GPIO0_14: J3.22 U10.7(B1)
EXP_GPIO0_14_LT: U10.2(A1) ; also on sheet 21
EXP_GPIO0_32: J3.30 R52.1
EXP_GPIO0_33: J3.31 U18.L17(GPMC0_OEN_REN)
EXP_GPIO0_36: J3.29 U18.M18(GPMC0_BE1N)
EXP_GPIO0_38: J3.16 U18.R17(GPMC0_WAIT1)
EXP_GPIO0_39: J3.18 U18.K17(GPMC0_WPN)
EXP_GPIO0_40/PR0_ECAP0_IN_APWM_OUT: J3.32 U18.K18(GPMC0_DIR)
EXP_GPIO0_41: J3.37 U18.M19(GPMC0_CSN0)
EXP_GPIO0_42: J3.13 U18.M21(GPMC0_CSN1)
EXP_GPIO1_22: J3.15 ; also on sheet 42
EXP_HAT_DETECT: J3.39 ; also on sheet 40
EXP_I2C2_SCL: J3.5 ; also on sheet 38
EXP_I2C2_SDA: J3.3 ; also on sheet 38
EXP_PS_3V3_EN: R286.2 U57.B2(ON) ; also on sheet 40
EXP_PS_5V0_EN: R271.2 U53.C2(ON) ; also on sheet 40
EXP_SPI0_CLK: J3.23 ; also on sheet 42
EXP_SPI0_CS0: J3.24 R290.2 ; also on sheet 42
EXP_SPI0_CS1: J3.26 R289.2 ; also on sheet 42
EXP_SPI0_D0: J3.19 ; also on sheet 42
EXP_SPI0_D1: J3.21 ; also on sheet 42
EXP_SPI2_CLK: J3.12 ; also on sheet 37
EXP_SPI2_CS0/EHRPWM0_A: J3.35 R287.2 ; also on sheet 37
EXP_SPI2_CS1: J3.11 R288.2 U18.A19(MCASP0_ACLKX)
EXP_SPI2_CS2: J3.36 R291.2 U18.B18(MCASP0_AXR1)
EXP_SPI2_D0: J3.40 ; also on sheet 37
EXP_SPI2_D1/ECAP2_IN_APWM_OUT: J3.38 ; also on sheet 37
EXP_UART5_RXD: J3.10 ; also on sheet 42
EXP_UART5_TXD: J3.8 ; also on sheet 42
GPIO_MCU_SoC_INTn: R573.1 U18.B9(MCU_MCAN1_RX) ; also on sheet 43
HFOSC0_CLKOUT_32K: U18.B10(WKUP_CLKOUT0) ; also on sheet 18
MCASP1_ACLKX_BUF: U18.L19(GPMC0_BE0N_CLE) ; also on sheet 40
MCASP1_AFSX_BUF: U18.R18(GPMC0_WAIT0) ; also on sheet 40
MCASP1_AXR0_BUF: U18.K19(GPMC0_WEN) ; also on sheet 40
MCASP1_AXR2: R51.2 R52.2 U18.L18(GPMC0_ADVN_ALE)
MCASP1_AXR2_BUF: R51.1 ; also on sheet 40
MCU_GPIO0_15: J8.10 R89.2
MCU_GPIO0_15_R: R88.2 R89.1 U18.D7(MCU_MCAN1_TX)
MCU_GPIO0_16: J8.11 R573.2
MCU_I2C0_SCL: J8.24 R388.2 R746.2 ; also on sheet 13
MCU_I2C0_SCL_RC: C585.2 R746.1 U18.E12(MCU_I2C0_SCL)
MCU_I2C0_SDA: J8.21 R391.2 R747.2 ; also on sheet 13
MCU_I2C0_SDA_RC: C586.2 R747.1 U18.D9(MCU_I2C0_SDA)
MCU_INTn: U18.E11(MCU_SPI0_CS0) ; also on sheet 13
MCU_MCAN0_RX: J8.22 U18.E8(MCU_MCAN0_RX)
MCU_MCAN0_TX: J8.16 U18.C7(MCU_MCAN0_TX)
MCU_OSC0_XI: R69.2 R71.2 U18.A12(MCU_OSC0_XI)
MCU_OSC0_XO: R74.2 R77.2 U18.A11(MCU_OSC0_XO)
MCU_RESETSTATz: J8.23 TP45.1(TP) ; also on sheet 42
MCU_SAFETY_ERRORz_1V8: TP9.1(TP) U10.3(A2) ; also on sheet 42
MCU_SAFETY_ERRORz_3V3: J8.26 U10.6(B2) ; also on sheet 13
MCU_SPI0_CLK: J8.18 R748.2
MCU_SPI0_CS1: J8.8 R580.1
MCU_SPI0_CS1_R: R580.2 U18.C11(MCU_SPI0_CS1)
MCU_SPI0_D0: J8.6 U18.A15(MCU_SPI0_D0)
MCU_SPI0_D1: J8.4 U18.B12(MCU_SPI0_D1)
MCU_UART0_CTS: U18.B11(MCU_UART0_CTSN) U33.9(3A)
MCU_UART0_CTS_3V3: U33.11(3B1) ; also on sheet 31
MCU_UART0_CTS_CONN: J8.12 U33.10(3B2)
MCU_UART0_MUX_OE: R141.1 U33.15(~{OE})
MCU_UART0_MUX_SEL: J10.2 R144.2 U33.1(S)
MCU_UART0_RTS: U18.D10(MCU_UART0_RTSN) U33.12(4A)
MCU_UART0_RTS_3V3: U33.14(4B1) ; also on sheet 31
MCU_UART0_RTS_CONN: J8.17 U33.13(4B2)
MCU_UART0_RX_3V3: U33.2(1B1) ; also on sheet 31
MCU_UART0_RXD: U18.D8(MCU_UART0_RXD) U33.4(1A)
MCU_UART0_RXD_CONN: J8.13 U33.3(1B2)
MCU_UART0_TX_3V3: U33.5(2B1) ; also on sheet 31
MCU_UART0_TXD: U18.F8(MCU_UART0_TXD) U33.7(2A)
MCU_UART0_TXD_CONN: J8.19 U33.6(2B2)
PMIC_LPM_EN0: R792.2 ; also on sheet 13
PMIC_WDOG_TRIGG: U18.D13(WKUP_I2C0_SCL) ; also on sheet 13
PR0_PRU0_GPO0: RA5.8 U18.N21(GPMC0_AD0)
PR0_PRU0_GPO1: RA5.7 U18.N20(GPMC0_AD1)
PR0_PRU0_GPO2: RA5.6 U18.N19(GPMC0_AD2)
PR0_PRU0_GPO3: RA5.5 U18.N18(GPMC0_AD3)
PR0_PRU0_GPO4: RA6.5 U18.N17(GPMC0_AD4)
PR0_PRU0_GPO5: RA6.6 U18.P18(GPMC0_AD5)
PR0_PRU0_GPO6: RA6.7 U18.P19(GPMC0_AD6)
PR0_PRU0_GPO7: RA6.8 U18.P21(GPMC0_AD7)
REFCLK1_R: R55.2 U18.A20(MCASP0_AFSX)
SoC_CLKIN: R69.1 ; also on sheet 25
SoC_I2C0_SCL: J3.28 ; also on sheet 10 13 22 42
SoC_I2C0_SDA: J3.27 ; also on sheet 10 13 22 42
SoC_I2C2_SCL: U18.M22(GPMC0_CSN2) ; also on sheet 38
SoC_I2C2_SDA: U18.M20(GPMC0_CSN3) ; also on sheet 38
SoC_RGMII_MDC: U18.V12(MDIO0_MDC) ; also on sheet 23 24
SoC_RGMII_MDIO: U18.V13(MDIO0_MDIO) ; also on sheet 23 24
SOC_SPI2_CLK: R782.2 ; also on sheet 37
SOC_SPI2_CS0: U18.B21(MCASP0_AFSR) ; also on sheet 37
SOC_SPI2_D0: U18.C19(MCASP0_AXR3) ; also on sheet 37
SOC_SPI2_D1: U18.B19(MCASP0_AXR2) ; also on sheet 37
SoC_VOUT0_DATA16: RA3.8 U18.P22(GPMC0_AD8) ; also on sheet 41
SoC_VOUT0_DATA17: RA3.7 U18.R19(GPMC0_AD9) ; also on sheet 41
SoC_VOUT0_DATA18: RA3.6 U18.R20(GPMC0_AD10) ; also on sheet 41
SoC_VOUT0_DATA19: RA3.5 U18.R22(GPMC0_AD11) ; also on sheet 41
SoC_VOUT0_DATA20: RA4.8 U18.T22(GPMC0_AD12) ; also on sheet 41
SoC_VOUT0_DATA21: RA4.7 U18.R21(GPMC0_AD13) ; also on sheet 41
SoC_VOUT0_DATA22: RA4.6 U18.T20(GPMC0_AD14) ; also on sheet 41
SoC_VOUT0_DATA23: RA4.5 U18.T21(GPMC0_AD15) ; also on sheet 41
VSEL_SD_SOC: R771.1 ; also on sheet 13
WKUP_LFOSCO_XI: C45.1 R764.2 U18.A8(WKUP_LFOSC0_XI) Y2.1
WKUP_LFOSCO_XO: C42.1 U18.A9(WKUP_LFOSC0_XO) Y2.2
WKUP_UART0_CTS_3V3: U18.C10(WKUP_UART0_CTSN) ; also on sheet 31
WKUP_UART0_RTS_3V3: U18.C8(WKUP_UART0_RTSN) ; also on sheet 31
WKUP_UART0_RX_3V3: U18.C9(WKUP_UART0_RXD) ; also on sheet 31
WKUP_UART0_TX_3V3: U18.E9(WKUP_UART0_TXD) ; also on sheet 31
N16906426: C33.1 R71.1 Y1.1
N16906432: C36.1 R74.1 Y1.3
N16931396: R270.2 U53.B2(CL)
N16931420: R281.1 U53.C1(OC)
N17492093: R40.2 U10.5(OE)
N17492111: J10.1 R392.1
N21761137: R792.1 TP41.1(TP) U18.D12(PMIC_LPM_EN0)
N24605533: R771.2 U18.N22(GPMC0_CLK)
N24625785: R748.1 U18.B13(MCU_SPI0_CLK)
N24649912: R782.1 U18.A21(MCASP0_ACLKR)

Not connected (* = marked no-connect by the designer): U18 E13(WKUP_I2C0_SDA)*

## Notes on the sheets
sheet 32
- D-Note:
  The only LFOSC0 register bits that should be changed by the
  customer are BP_C, PD_C and CTRLMMR_WKUP_LFXOSC_TRIM[18:16],
  where PD_C is reset (0) to enable the oscillator and the
  BP_C bit is only set (1) to place the oscillator in bypass
  mode when using an LVCMOS clock source. The
  CTRLMMR_WKUP_LFXOSC_TRIM[18:16] bits are set based on the
  actual capacitance load applied to the crystal, as defined
  by the Load Capacitance Equation. The load capacitance range
  of the crystal will be half of the recommended capacitor
  value range, since they are connected in series with the
  crystal resonant circuit.
- D-Note:
  Open-drain output type buffer I2C interfaces have
  slew rate requirement specified when pulled to 3.3 V.
  An RC is used to limit the slew rate
- SOC WKUP DOMAIN
- D-Note:
  WKUP_CLKOUT0 is a buffered
  output of the high frequency
  oscillator (HFOSC0, 25MHz)
  available after reset as default
  output.
- D-Note:
  SOC IO buffers used for GPMC interface signals are disabled
  during reset. The required pulls for the interfaced signals
  are provided on the GPMC interface card
- D-Note:
  WKUP_LFOSC0 has limited
  use case. Populate 0E (ohms) to
  ground XI when LFOSC0 is
  not used. Refer to the
  SoC datasheet.
- ECS-.327-9-34QCS-TR
- SOC GPMC INTERFACE
- C
- D-Note:
  SOC IO buffers used for GPMC interface signals are disabled
  during reset. The required pulls for the interfaced signals
  are provided on the GPMC interface card
- C
- D-Note:
  Shorting of multiple boot mode inputs (IOs)
  together is not recommended or allowed
  since the IOs have alternative functions
  that could be configured after booting.
  Shorting the boot mode pins directly to VCC
  or ground is not recommended. Connect each
  of the boot mode pins through separate
  resistors. Choose the boot mode resistor
  value based on the use case (10K or
  similar).
- D-Note:
  Connect PMIC_LPM_EN0 signal from SOC to PMIC EN through a
  pullup placed near the PMIC input pin through a 0E (ohm)
  series resistor for isolation. DNI the series resistor
  when partialIO functionality is not implemented. If the
  application will not use any of the AM62 low power modes,
  then the PMIC_LPM_EN0 does not have to be connected to the PMIC.
- D-Note:
  Addition of Series and Parallel resistors. Refer to the
  processor data sheet for the recommended circuit configuration
  for pre-production boards and production boards.
- D-Note:
  LVCMOS IO buffers used to implement
  GPMC interface are off during reset
  and after reset until the host
  configures the interface. The
  recommendation is to add pulls for
  memory interface signals that can
  float. The required pulls for the
  GPMC interface signals are added on
  the GPMC interface add-on card.
- GPIO_43
- GPIO_44
- To User Exp hdr
- D-Note:
  Delete or reduce the series resistor value to 0E (ohms) when buffers are not
  used. The series resistors can be used to isolate the alternative function
  for testing the bootmode configuration.
- GPIO0_40
- D-Note:
  When the boot mode isolation buffers are not
  used, connect the boot mode configuration
  resistors directly to the SoC boot mode input
  pins. Connect the SoC bootmode signal used for
  alternative function to the attached device
  through 0E (ohms) for isolation or testing.
- BOOTMODE PINS
- Signals from Bootmode buffer
- HDMI
- McASP1
- MUX
- AUDIO
- M.2 Wilink BT
- BUF
- D-Note:
  1. 1k resistor at the output of the buffer is recommended when the bootmode
  pins are used for alternate functions to limit the buffer current
  2. When bootmode isolation buffers are not used, connect the bootmode
  configuration resistors directly to the SoC bootmode input pins. Connect the
  SOC bootmode signal used for alternate function to the attached device
  through 0E (ohms) for isolation or testing.
- D-Note:
  Connect SYS_BOOTMODE signals (output) from
  BOOTMODE configuration resistors and switches
  when bootmode buffers are not used
- R-Note:
  Series resistors are used to
  isolate the SoC BOOTMODE input
  control logic after the BOOTMODE
  inputs value is latched.
sheet 33
- USER EXPANSION CONNECTOR
- D-Note:
  SoC IO buffers are off during reset. A parallel pull is recommended near
  to the attached device input that is being driven by the SoC IO (input does not float).
- D-Note:
  Any SoC IO that has a trace connected but not being
  driven actively needs to be connected to an external
  pull. When adding pull is not feasible, ensure that the
  traces are routed away from noisy signals.
- GPIO1_10
- GPIO1_9
- GPIO1_7
- GPIO1_8
- D-Note:
  Add-on boards are expected to take care of the
  connection polarity for  for the UART signals
  (cross-over of RX and TX or other signals).
- GPIO1_14
- C
- GPIO1_13
- R-Note:
  These supplies are off
  by default. The supplies
  are controlled by the below
  load switches and need to
  be enabled.
- CAD Note:
  R55 (Series damping resistor) should be placed closer to the SoC.
- D-Note:
  Processor IOs connected to USER EXPANSION CONNECTOR
  are not fail-safe. No external input shall be applied
  when the starter kit is not powered-up.
- SoC_I2C2_SCL
- SoC_I2C2_SDA
- GPIO0_43
- GPIO0_44
- GPIO1_30
- GPIO1_24
- GPIO1_25
- GPIO1_11
- GPIO1_14
- GPIO0_42
- GPIO1_22
- GPIO0_38
- GPIO1_18
- GPIO0_39
- GPIO1_19
- GPIO0_14
- GPIO1_17
- GPIO1_15
- GPIO1_16
- GPIO1_27
- GPIO1_26
- GPIO0_33
- GPIO0_36
- GPIO0_32
- GPIO0_40
- MCASP1_AXR2
- GPIO1_10
- PWM required as per RPi sheet
  NA in Pinmux
- GPIO1_13
- GPIO1_9
- GPIO0_41
- GPIO1_8
- GPIO1_7
- Silk: USER EXPN
- LOAD SWITCHES FOR USER EXPANSION CONNECTOR
- D-Note:
  Load Switch is sized to
  source up to 150mA current
- D-Note:
  Load Switch is sized to
  source up to 500mA current
- V
- V
- R-Note:
- The Starter Kit shall not be powered through the 5V0 or 3V3 supply pins on the 40-pin User Expansion Connector
  (the pins are output supply).
  User Expansion Connector I/O are not fail-safe and shall not be driven when AM62P Starter Kit is
  not powered.
  5V supply on User Expansion Connector can source 150mA max.
  3V3 supply on User Expansion Connector can source 500mA max.
- It should be connected to PORz of the SoC TBD
sheet 34
- D-Note:
  Open-drain output type buffer I2C interfaces have slew rate
  requirement specified when pulled to 3.3 V. An RC is used
  to limit the slew rate
- D-Note:
  MCU_I2C0
  A pull-up is recommended for open-drain output
  type I2C interfaces, irrespective of the IO usage
  or IO configuration. Refer to the Pin Connectivity
  Requirements table of the SoC datasheet.
- D-Note:
  SoC IO buffers are off during reset.
  A parallel pull is recommended near
  to the attached device input that is
  being driven by the SoC IO
  (input does not float).
- D-Note:
  Y1 recommended crystal part number:
  Change the part number of Y1 to
  ABM11W-25.0000MHZ-8-D1X-T3
  Update DNI caps C305 and C303 to 12 pF
- D-Note :-
  Logic HIGH to LOW transition on this signal
  records a CANUART I/O Wakeup Event
- SOC - MCU DOMAIN
- CAD Note :-
  R69 TRI-PAD WITH R71
- CAD Note :-
  R76 TRI-PAD WITH R73
- D-Note:
  Connect the 25 MHz crystal directly to the SoC XI and XO pins (no series or parallel resistors are recommended). The internal
  oscillator implements AGC (Automatic Gain Control) for amplitude control. Match the SoC and the EPHY crystal specs.
- C
- D-Note:
  Refer to Applications, Implementation, and Layout section of the processor-specific data sheet for clock routing guidelines as below:
  Clock Routing Guidelines - Oscillator Routing
- D-Note:
  No HFOSC0 registers are required to be changed. These registers should remain in their default state. Select the
  appropriate crystal circuit components that are compliant to the values defined in the MCU_OSC0 Crystal Circuit
  Requirements table. Read the Load Capacitance and Shunt Capacitance sections to select the appropriate crystal
  circuit components.
- CAD Note :-
  R74 TRI-PAD WITH R77
- D-Note:
  MCU_OSC0 has been validated only with a 25 MHz clock source, so that is the only frequency supported. The datasheet shows
  MCU_OSC0 not starting until after the core voltage, because there are some cases where the oscillator may not start until
  VDD_CORE is valid. In most cases it will start as early as VDDS_OSC0, but this may not always be the case. This diagram in
  the datasheet is showing the maximum start-up time, which must include the case where the delay is based on VDD_CORE being
  valid.
- D-Note:
  Ground XO when an external
  oscillator is used. Refer to
  the SoC data sheet for the
  recommended connection.
- SOC-MCU HEADER
- D-Note:
  Any SoC IO that has a trace connected but not being
  driven actively needs to be connected to an external
  pull. When adding pull is not feasible, ensure that the
  traces are routed away from noisy signals.
- C
- D-Note:
  Processor IOs connected to MCU
  expansion CONNECTOR are not fail-safe.
  No external input shall be applied when
  when Starter Kit/EVM is not powered-up.
- Silk: MCU HDR
- SOC-MCU_UART0 MUX
- C
- V
- INPUT/OUTPUT
- OEn
- SEL
- An
- L
- L(DEFAULT)
- An=nB1
- SOC - FT4232
- L
- H
- An=nB2
- SOC - MCU HEADER
